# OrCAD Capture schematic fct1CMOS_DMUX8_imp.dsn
size A
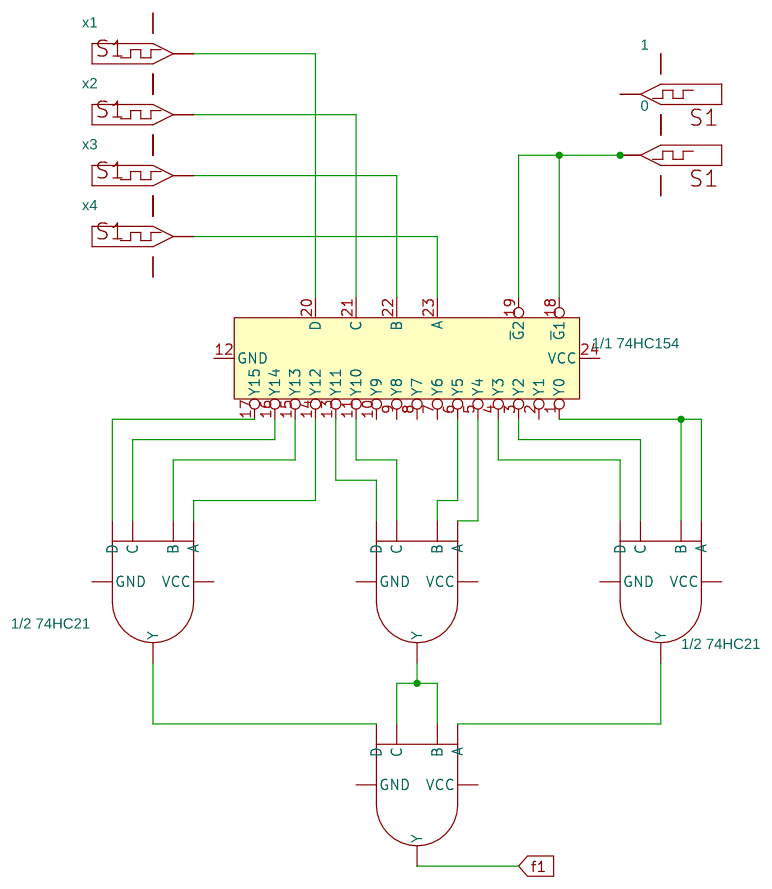
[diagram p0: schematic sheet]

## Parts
0  DigStim1
1  DigStim1
U1  1/1 74HC154  [DIP.100/24/W.300/L1.250]
U2  1/2 74HC21  [DIP.100/14/W.300/L.800]  (sections A,B)
U5  74HC21  [DIP.100/14/W.300/L.800]  (section B)
U6  1/2 74HC21  [DIP.100/14/W.300/L.800]  (section A)
x1  DigStim1
x2  DigStim1
x3  DigStim1
x4  DigStim1

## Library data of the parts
0 1 x1-x4 = DigStim1
U1 = 74HC154
U2 U5 U6 = 74HC21

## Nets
GND: 0.3(GND) 1.3(GND) U1.12(GND) U2.7(GND) U5.7(GND) U6.7(GND) x1.3(GND) x2.3(GND) x3.3(GND) x4.3(GND)
VCC: 0.2(VCC) 1.2(VCC) U1.24(VCC) U2.14(VCC) U5.14(VCC) U6.14(VCC) x1.2(VCC) x2.2(VCC) x3.2(VCC) x4.2(VCC)
f1: U5.8(Y)
N17580: 0.OUT U1.18(~{G}1) U1.19(~{G}2)
N17608: U1.23(A) x4.OUT
N17615: U1.22(B) x3.OUT
N17622: U1.21(C) x2.OUT
N17648: U1.20(D) x1.OUT
N18121: U2.6(Y) U5.13(D)
N18156: U1.1(Y0) U6.1(A) U6.2(B)
N18163: U1.3(Y2) U6.4(C)
N18175: U1.4(Y3) U6.5(D)
N18196: U1.5(Y4) U2.9(A)
N18209: U1.6(Y5) U2.10(B)
N18221: U1.11(Y10) U2.12(C)
N18233: U1.13(Y11) U2.13(D)
N18245: U1.17(Y15) U2.5(D)
N18252: U1.16(Y14) U2.4(C)
N18267: U1.15(Y13) U2.2(B)
N18280: U1.14(Y12) U2.1(A)
N18560: U2.8(Y) U5.10(B) U5.12(C)
N18564: U5.9(A) U6.6(Y)

Not connected (* = marked no-connect by the designer): 1 OUT; U1 2(Y1) 7(Y6) 8(Y7) 9(Y8) 10(Y9)
